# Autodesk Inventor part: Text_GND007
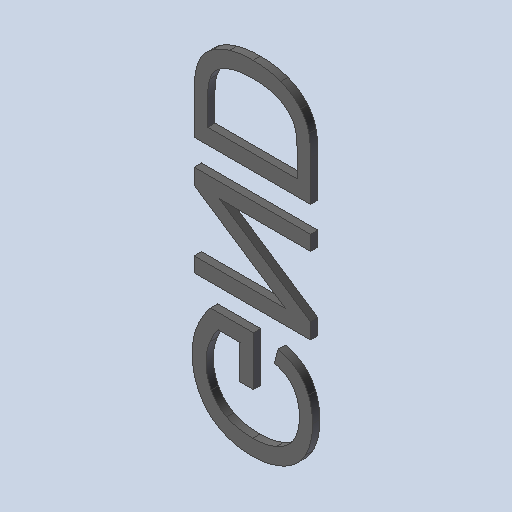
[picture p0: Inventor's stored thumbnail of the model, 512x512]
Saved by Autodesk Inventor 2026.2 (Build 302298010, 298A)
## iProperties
Created: 2026-10
Part Number: Text_GND007
Material: Générique
Document SubType Name: Modeling
Designer: mel
Density: 1 g/cm^3
Appearance: Par défaut
Author: mel
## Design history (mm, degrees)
feature "Base1"
feature "Base2"
feature "Base3"
node "Solide1"
node "Solide2"
node "Solide3"
